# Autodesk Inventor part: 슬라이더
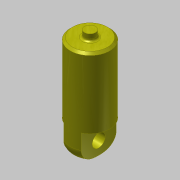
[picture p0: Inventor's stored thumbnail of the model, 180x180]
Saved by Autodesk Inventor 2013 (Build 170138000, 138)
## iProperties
Created: 2016-08
Part Number: 슬라이더
Material: 강철, 탄소
Document SubType Name: Modeling
Designer: mduedu
Density: 7.87 g/cm^3
Mass: 75.783 g
Surface Area: 29.7233 cm^2
Volume: 9.62935 cm^3
Author: mduedu
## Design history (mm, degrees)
sketch "스케치1"
  geometry: C1 r 9 at (0, 0); 1 further point
  constraints: 1 centre point, 1 coincident
  dimensions: "d0" = 18 diameter of C1
extrude "돌출1" new body sketch "스케치1" distance "d1" = 45; taper "d2" = 0 deg
fillet "모깎기1" dims "d21" = 6
sketch "스케치6"
  geometry: L1 (9, 6)-(9, 45) reference; L2 (-9, 6)-(-9, 45) reference; L3 (9, 45)-(-9, 45) reference; L4 (0, 45)-(0, 0); L5 (9, 13)-(4, 13); L6 (4, 13)-(4, 0); L7 (4, 0)-(9, 0); L8 (9, 0)-(9, 13); L9 (-9, 13)-(-4, 13); L10 (-4, 13)-(-4, 0); L11 (-4, 0)-(-9, 0); L12 (-9, 0)-(-9, 13)
  constraints: 18 end point, 4 symmetric about line, 2 parallel, 2 perpendicular, 1 horizontal, 1 horizontal alignment, 1 midpoint, 1 point on line
  dimensions: "d22" = 13 distance of L7.end L5.start; "d24" = 4 distance between parallel lines of L6 L4
extrude "돌출5" cut sketch "스케치6" stored distance "d25" = 8; taper "d26" = 0 deg
sketch "스케치8"
  geometry: C1 r 3 at (6, 0); 1 further point
  constraints: 1 centre point, 1 horizontal alignment
  dimensions: "d27" = 6 diameter of C1; "d28" = 6 distance of point (0, 0) C1.centre
extrude "돌출6" cut sketch "스케치8" stored distance "d29" = 8; taper "d30" = 0 deg
chamfer "모따기2" distance "d43" = 1; stored, may be unused: second distance "d44" = 2, angle "d45" = 30 deg
sketch "스케치9"
  geometry: C1 r 2.5 at (0, 0); 1 further point
  constraints: 1 centre point, 1 coincident
  dimensions: "d47" = 5 diameter of C1
extrude "돌출7" join sketch "스케치9" distance "d48" = 3; taper "d49" = 0 deg
fillet "모깎기2" dims "d50" = 1
node "솔리드1"
